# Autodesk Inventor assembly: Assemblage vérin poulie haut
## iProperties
Created: 2011-02
Part Number: Assemblage vérin poulie haut
Document SubType Name: Assembly
Designer: eric
Norme de conversion: IGES 5.3
Nom du fichier: No Iges File Name specified
Préprocesseur: Autodesk Inventor 2011
Postprocesseur: Build: 342, Release: 2008 SP3 - Date: Tue 05/27/2008
Unités envoyées: MM
Incertitude: 0.01
Author: eric
